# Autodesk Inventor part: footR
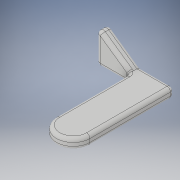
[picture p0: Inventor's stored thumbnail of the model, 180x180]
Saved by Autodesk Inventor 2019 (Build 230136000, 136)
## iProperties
Created: 2020-09
Part Number: footR
Material: 一般
Document SubType Name: Modeling
Designer: kikut
Density: 1 g/cm^3
Appearance: 既定
Author: kikut
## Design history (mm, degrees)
sketch "スケッチ1"
  geometry: L1 (-0.01, -0.1)-(0.01, -0.1); L2 (0.01, -0.1)-(0.01, -0.05); L3 (0.01, -0.05)-(-0.01, -0.05); L4 (-0.01, -0.05)-(-0.01, -0.1); L5 (-0.01, -0.1)-(0.01, -0.05); L6 (0.01, -0.1)-(-0.01, -0.05); L7 (0, -0.12)-(0, 0.02) reference; A1 r 0.01 centre (0, -0.05) between (0.01, -0.05) and (-0.01, -0.05); 2 further points
  constraints: 12 end point, 4 midpoint, 2 parallel, 2 point on circle, 1 centre point, 1 horizontal, 1 perpendicular, 1 other
  dimensions: "d0" = 0.05 distance of L1.end L2.end; "d1" = 0.05 distance from line of L3 point (0, 0); "d2" = 0.02 distance of L2.end L3.end
extrude "押し出し1" new body sketch "スケッチ1" stored distance "d3" = 0.006; taper "d4" = 0 deg
sketch "スケッチ4"
  geometry: L1 (0, -0.006)-(0.02, -0.006) reference; L2 (0.02, -0.006)-(0.04, -0.006); L3 (0.04, -0.006)-(0.04, 0.014); L4 (0.02, 0)-(0, 0) reference; L5 (0.04, 0.014)-(0.02, 0); L6 (0.02, 0)-(0.02, -0.006); 1 further point
  constraints: 8 end point, 1 horizontal, 1 parallel, 1 perpendicular
  dimensions: "d17" = 0.02 distance of L1.end L2.end; "d18" = 0.02 distance of L2.end L3.end
extrude "押し出し4" join sketch "スケッチ4" distance "d19" = 0.006; taper "d20" = 0 deg
fillet "フィレット5" dims "d21" = 0.002
fillet "フィレット6" dims "d22" = 0.002
fillet "フィレット7" dims "d23" = 0.002
node "ソリッド1"
